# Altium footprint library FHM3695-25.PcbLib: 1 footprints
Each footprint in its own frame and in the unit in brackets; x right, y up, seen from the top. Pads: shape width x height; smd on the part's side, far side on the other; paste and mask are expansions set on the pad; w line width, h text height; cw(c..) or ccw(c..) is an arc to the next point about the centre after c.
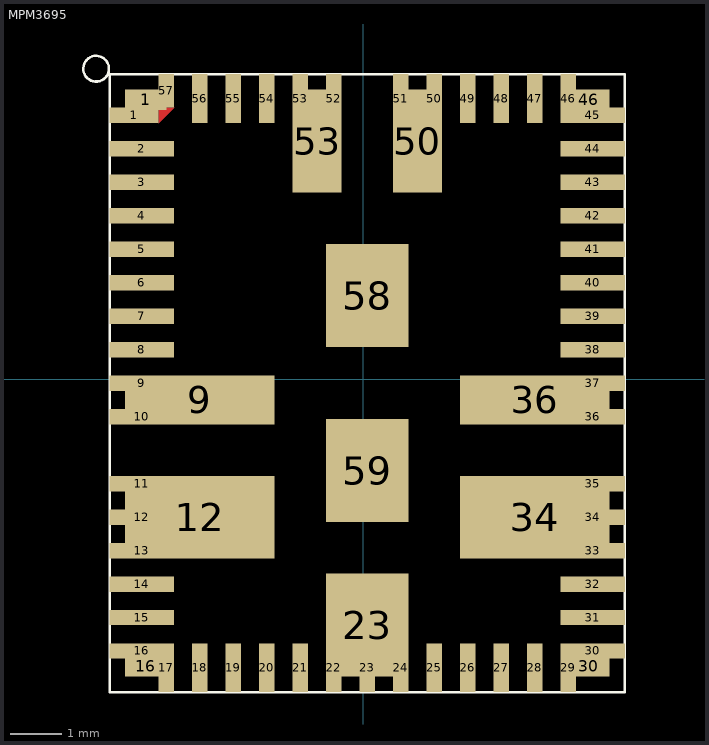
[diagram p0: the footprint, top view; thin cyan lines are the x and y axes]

## MPM3695 [mm]
pads (70):
  rect 0.95x0.3 smd paste-0.06 mask+0: 1(-4.45,5.125)
  rect 0.8x0.4 smd paste-0.06 mask+0: 1(-4.225,5.425) 16(-4.225,-5.575) 30(4.375,-5.575) 46(4.375,5.425)
  rect 1.25x0.3 smd paste-0.04 mask+0: 2(-4.3,4.475) 3(-4.3,3.825) 4(-4.3,3.175) 5(-4.3,2.525) 6(-4.3,1.875) 7(-4.3,1.225) 8(-4.3,0.575) 9(-4.3,-0.075) 10(-4.3,-0.725) 11(-4.3,-2.025) 12(-4.3,-2.675) 13(-4.3,-3.325) 14(-4.3,-3.975) 15(-4.3,-4.625) 16(-4.3,-5.275) 30(4.45,-5.275) 31(4.45,-4.625) 32(4.45,-3.975) 33(4.45,-3.325) 34(4.45,-2.675) 35(4.45,-2.025) 36(4.45,-0.725) 37(4.45,-0.075) 38(4.45,0.575) 39(4.45,1.225) 40(4.45,1.875) 41(4.45,2.525) 42(4.45,3.175) 43(4.45,3.825) 44(4.45,4.475) 45(4.45,5.125)
  rect 2.9x0.95 smd paste-0.12 mask+0: 9(-3.175,-0.4) 36(3.325,-0.4)
  rect 2.9x1.6 smd paste-0.24 mask+0: 12(-3.175,-2.675) 34(3.325,-2.675)
  rect 0.3x0.95 smd paste-0.04 mask+0: 17(-3.825,-5.6) 18(-3.175,-5.6) 19(-2.525,-5.6) 20(-1.875,-5.6) 21(-1.225,-5.6) 22(-0.575,-5.6) 23(0.075,-5.6) 24(0.725,-5.6) 25(1.375,-5.6) 26(2.025,-5.6) 27(2.675,-5.6) 28(3.325,-5.6) 29(3.975,-5.6) 46(3.975,5.45) 47(3.325,5.45) 48(2.675,5.45) 49(2.025,5.45) 50(1.375,5.45) 51(0.725,5.45) 52(-0.575,5.45) 53(-1.225,5.45) 54(-1.875,5.45) 55(-2.525,5.45) 56(-3.175,5.45)
  rect 1.6x2 smd paste-0.24 mask+0: 23(0.075,-4.775) 58(0.075,1.625) 59(0.075,-1.775)
  rect 0.95x2 smd paste-0.24 mask+0: 50(1.05,4.625) 53(-0.9,4.625)
  rect 0.3x0.65 smd paste-0.06 mask+0: 57(-3.825,5.6)
Top Layer:
  region: -3.675,5.275 -3.975,5.275 -3.975,4.975
Top Overlay:
  lines w0.05: -5.099,6.264 ccw(c-5.189,6.031) -5.078,6.255 ; -4.925,-6.075 5.075,-6.075 5.075,5.925 -4.925,5.925 -4.925,-6.075
3D body: height 0, standoff -4.32, extent -5.025,-6.025 4.975,5.975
